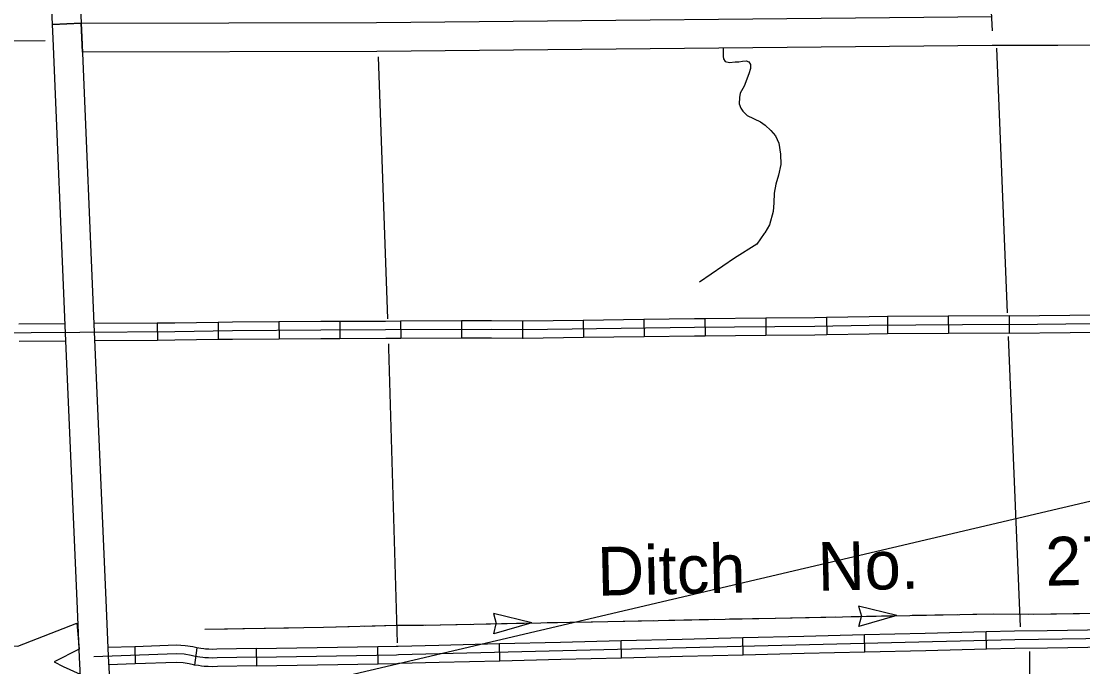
# Model space of a CAD drawing. Extents: x -5566 to 1759129, y -3726 to 731467.
# Drawn here: x -4997.6 to -4927.6, y 268.1 to 310.6 of the extents above; entities that cross this region are included whole.
import ezdxf

# ---------------------------------------------------------------- set-up
doc = ezdxf.new("R2010")
doc.units = 0
doc.layers.add('Default', color=7, linetype='Continuous')

msp = doc.modelspace()

# ---------------------------------------------------------------- linework, layer by layer
at = {"layer": 'Default'}
for p, q in [((-5037.982, 253.015), (-4814.177, 305.513)), ((-4952.518, 291.013), (-4952.507, 289.874)), ((-4948.508, 291.051), (-4948.498, 289.911)), ((-4944.505, 291.095), (-4944.483, 289.956)), ((-4940.489, 291.158), (-4940.48, 290.019)), ((-4936.479, 291.189), (-4936.47, 290.05)), ((-4932.469, 291.219), (-4932.461, 290.08)), ((-4988.603, 290.73), (-4988.594, 289.591)), ((-4984.598, 290.783), (-4984.58, 289.644)), ((-4980.583, 290.815), (-4980.577, 289.675)), ((-4976.573, 290.836), (-4976.567, 289.696)), ((-4972.563, 290.855), (-4972.558, 289.716)), ((-4968.553, 290.874), (-4968.548, 289.735)), ((-4964.536, 290.868), (-4964.545, 289.729)), ((-4960.539, 290.916), (-4960.524, 289.777)), ((-4956.529, 290.966), (-4956.515, 289.827)), ((-4963.921, 270.989), (-4966.452, 271.613)), ((-4966.452, 271.613), (-4966.259, 270.947)), ((-4939.868, 271.47), (-4942.398, 272.094)), ((-4942.398, 272.094), (-4942.205, 271.428)), ((-4939.868, 271.47), (-4942.371, 270.745)), ((-4942.371, 270.745), (-4942.205, 271.419)), ((-4963.921, 270.989), (-4966.425, 270.264)), ((-4966.425, 270.264), (-4966.259, 270.938)), ((-4949.987, 268.888), (-4950.015, 270.027)), ((-4941.97, 269.086), (-4941.998, 270.224)), ((-4933.953, 269.283), (-4933.981, 270.422)), ((-4990.087, 269.423), (-4990.047, 268.285)), ((-4985.993, 269.343), (-4986.155, 268.215)), ((-4974.042, 268.304), (-4974.063, 269.443)), ((-4966.021, 268.494), (-4966.049, 269.633)), ((-4958.004, 268.691), (-4958.032, 269.83)), ((-4982.079, 269.298), (-4982.063, 268.159))]:
    msp.add_line(p, q, dxfattribs=at)
for points in [[(-4993.615, 310.476), (-4995.511, 310.392), (-4996.003, 321.585), (-4997.259, 349.695), (-4998.481, 377.677), (-4998.548, 379.506), (-4998.756, 386.137), (-4999.305, 409.605), (-4999.405, 414.253)], [(-4997.507, 414.294), (-4997.407, 409.647), (-4996.858, 386.189), (-4996.65, 379.571), (-4996.584, 377.753), (-4995.362, 349.779), (-4994.106, 321.669), (-4993.615, 310.476)], [(-4935.136, 340.268), (-4934.932, 340.239), (-4934.712, 340.118), (-4934.597, 339.963), (-4934.55, 339.818), (-4934.52, 339.683), (-4934.512, 339.514), (-4934.542, 339.298), (-4934.537, 339.124), (-4934.44, 333.834), (-4934.306, 328.927), (-4934.137, 324.131), (-4933.786, 313.783), (-4933.595, 309.971)], [(-4894.213, 311.471), (-4894.177, 309.573), (-4894.454, 309.568), (-4900.14, 309.548), (-4902.933, 309.43), (-4913.232, 309.209), (-4915.299, 309.191), (-4922.772, 309.057), (-4929.257, 309.022), (-4933.595, 309.022)], [(-4993.533, 308.577), (-4993.615, 310.476), (-4974.148, 310.525), (-4933.595, 310.92)], [(-4995.511, 310.392), (-4993.615, 310.476), (-4993.575, 309.565), (-4992.757, 290.162), (-4991.964, 271.99), (-4991.839, 268.804), (-4991.604, 264.558), (-4990.974, 248.26), (-4990.443, 236.483), (-4990.139, 228.112)], [(-4992.036, 228.043), (-4992.34, 236.405), (-4992.871, 248.181), (-4993.501, 264.469), (-4993.735, 268.714), (-4993.861, 271.911), (-4994.654, 290.081), (-4995.471, 309.483), (-4995.511, 310.392)], [(-4932.093, 269.898), (-4922.733, 270.032), (-4914.418, 270.04), (-4914.277, 270.034), (-4914.082, 270.022), (-4913.941, 269.997), (-4913.709, 269.942), (-4913.495, 269.906), (-4913.311, 269.869), (-4913.036, 269.851), (-4912.639, 269.9), (-4912.388, 269.942), (-4912.125, 270.004), (-4912.015, 270.052), (-4911.918, 270.138), (-4911.881, 270.23), (-4911.887, 270.371), (-4911.905, 270.731), (-4911.991, 272.12), (-4912.699, 290.852), (-4913.247, 310.158)], [(-5014.656, 309.149), (-5005.512, 309.311), (-4995.997, 309.342)], [(-4933.595, 309.022), (-4974.136, 308.626), (-4993.533, 308.577)], [(-4951.316, 308.849), (-4951.322, 308.301), (-4951.286, 308.134), (-4951.184, 307.963), (-4950.898, 307.895), (-4950.522, 307.944), (-4950.274, 307.939), (-4950.041, 307.983), (-4949.796, 308.012), (-4949.626, 307.943), (-4949.507, 307.756), (-4949.504, 307.504), (-4949.626, 307.14), (-4949.935, 306.33)], [(-4933.309, 308.843), (-4932.596, 291.415)], [(-4974.038, 308.258), (-4973.428, 291.024)], [(-4949.935, 306.33), (-4950.186, 305.877), (-4950.242, 305.585), (-4950.248, 305.18), (-4950.153, 304.893), (-4950.007, 304.686), (-4949.722, 304.408), (-4948.852, 303.986), (-4948.547, 303.777), (-4948.166, 303.411), (-4947.87, 303.057), (-4947.637, 302.578), (-4947.524, 301.85), (-4947.519, 301.17), (-4947.672, 300.469), (-4947.846, 299.874), (-4947.959, 299.297), (-4947.97, 298.655), (-4948.023, 298.08), (-4948.268, 297.207), (-4948.558, 296.676), (-4948.611, 296.624), (-4949.084, 295.925), (-4950.568, 295.016), (-4952.874, 293.439)], [(-4952.518, 291.013), (-4953.202, 291.007), (-4956.529, 290.966)], [(-4948.508, 291.051), (-4952.518, 291.013)], [(-4944.505, 291.095), (-4945.278, 291.081), (-4948.508, 291.051)], [(-4940.489, 291.158), (-4941.696, 291.149), (-4944.505, 291.095)], [(-4936.479, 291.189), (-4940.489, 291.158)], [(-4932.469, 291.219), (-4936.479, 291.189)], [(-4932.469, 291.219), (-4928.462, 291.262)], [(-4928.462, 291.262), (-4924.452, 291.306)], [(-4994.679, 290.684), (-4997.719, 290.661)], [(-4932.465, 290.65), (-4941.688, 290.58), (-4945.27, 290.511), (-4953.196, 290.437), (-4964.484, 290.298), (-4966.576, 290.314), (-4973.552, 290.281), (-4977.83, 290.26), (-4983.643, 290.228), (-4987.447, 290.169), (-4993.705, 290.121)], [(-4988.603, 290.73), (-4992.779, 290.698)], [(-4984.598, 290.783), (-4987.454, 290.738), (-4988.603, 290.73)], [(-4980.583, 290.815), (-4983.649, 290.798), (-4984.598, 290.783)], [(-4976.573, 290.836), (-4977.833, 290.829), (-4980.583, 290.815)], [(-4972.563, 290.855), (-4973.554, 290.85), (-4976.573, 290.836)], [(-4968.553, 290.874), (-4972.563, 290.855)], [(-4964.536, 290.868), (-4966.575, 290.884), (-4968.553, 290.874)], [(-4960.539, 290.916), (-4964.485, 290.868), (-4964.536, 290.868)], [(-4956.529, 290.966), (-4960.539, 290.916)], [(-4932.465, 290.65), (-4923.163, 290.75), (-4912.699, 290.852)], [(-4993.705, 290.121), (-5009.708, 290), (-5010.205, 289.956), (-5010.678, 289.894), (-5011.158, 289.828), (-5011.69, 289.749), (-5012.214, 289.661), (-5012.995, 289.454), (-5013.768, 289.196), (-5014.458, 288.94), (-5014.999, 288.722), (-5015.413, 288.535), (-5015.671, 288.419), (-5016.467, 287.979), (-5018.023, 286.931), (-5036.624, 273.349), (-5039.143, 271.485), (-5040.285, 270.723), (-5040.649, 270.529), (-5041.1, 270.226), (-5041.309, 270.024), (-5041.41, 269.807), (-5041.457, 269.628)], [(-4988.594, 289.591), (-4992.73, 289.559)], [(-4984.58, 289.644), (-4987.44, 289.599), (-4988.594, 289.591)], [(-4980.577, 289.675), (-4983.637, 289.659), (-4984.58, 289.644)], [(-4976.567, 289.696), (-4977.827, 289.69), (-4980.577, 289.675)], [(-4972.558, 289.716), (-4973.549, 289.711), (-4976.567, 289.696)], [(-4968.548, 289.735), (-4972.558, 289.716)], [(-4964.545, 289.729), (-4966.577, 289.745), (-4968.548, 289.735)], [(-4960.524, 289.777), (-4964.483, 289.728), (-4964.545, 289.729)], [(-4956.515, 289.827), (-4960.524, 289.777)], [(-4952.507, 289.874), (-4953.19, 289.868), (-4956.515, 289.827)], [(-4948.498, 289.911), (-4952.507, 289.874)], [(-4944.483, 289.956), (-4945.262, 289.941), (-4948.498, 289.911)], [(-4940.48, 290.019), (-4941.68, 290.01), (-4944.483, 289.956)], [(-4936.47, 290.05), (-4940.48, 290.019)], [(-4932.461, 290.08), (-4936.47, 290.05)], [(-4932.531, 289.842), (-4931.749, 270.735)], [(-4932.459, 290.08), (-4928.449, 290.123)], [(-4928.449, 290.123), (-4924.44, 290.167)], [(-4994.63, 289.545), (-4997.71, 289.521)], [(-4973.369, 289.366), (-4973.359, 289.08), (-4972.803, 269.681)], [(-4985.469, 270.571), (-4977.649, 270.703), (-4972.841, 270.847), (-4971.058, 270.847), (-4933.509, 271.597), (-4931.175, 271.558)], [(-4942.874, 271.41), (-4939.868, 271.47)], [(-4938.866, 271.49), (-4937.362, 271.52)], [(-4937.362, 271.52), (-4935.859, 271.55)], [(-4934.857, 271.57), (-4933.509, 271.597), (-4931.85, 271.57)], [(-4931.175, 271.558), (-4916.597, 271.788), (-4912.586, 271.557), (-4911.247, 270.793)], [(-4930.848, 271.564), (-4927.841, 271.611)], [(-5019.032, 269.984), (-5016.718, 269.908), (-4997.779, 269.465), (-4993.903, 270.979), (-4993.756, 269.252)], [(-4978.954, 270.681), (-4977.649, 270.703), (-4975.948, 270.754)], [(-4974.946, 270.784), (-4972.841, 270.847), (-4971.939, 270.847)], [(-4970.937, 270.849), (-4967.93, 270.909)], [(-4966.928, 270.929), (-4963.921, 270.989)], [(-4962.919, 271.009), (-4961.416, 271.039)], [(-4961.416, 271.039), (-4959.912, 271.069)], [(-4958.91, 271.089), (-4955.904, 271.149)], [(-4954.901, 271.169), (-4951.895, 271.229)], [(-4950.892, 271.249), (-4947.886, 271.309)], [(-4946.883, 271.33), (-4943.877, 271.39)], [(-4985.469, 270.571), (-4983.966, 270.597)], [(-4982.963, 270.614), (-4979.956, 270.664)], [(-4954.024, 269.929), (-4950.015, 270.027)], [(-4950.015, 270.027), (-4946.007, 270.126)], [(-4946.007, 270.126), (-4941.998, 270.224)], [(-4941.998, 270.224), (-4937.99, 270.323)], [(-4937.99, 270.323), (-4933.981, 270.422)], [(-4933.981, 270.422), (-4932.104, 270.468), (-4929.966, 270.498)], [(-4929.966, 270.498), (-4925.957, 270.555)], [(-4990.087, 269.423), (-4991.861, 269.361)], [(-4985.993, 269.343), (-4985.995, 269.343), (-4986.263, 269.409), (-4986.771, 269.491), (-4987.342, 269.519), (-4990.087, 269.423)], [(-4982.079, 269.298), (-4984.669, 269.26), (-4984.947, 269.247), (-4985.196, 269.26), (-4985.419, 269.266), (-4985.532, 269.281), (-4985.728, 269.305), (-4985.993, 269.343)], [(-4982.079, 269.298), (-4978.072, 269.37)], [(-4982.071, 268.728), (-4972.838, 268.896), (-4972.709, 268.899), (-4932.093, 269.898)], [(-4978.072, 269.37), (-4974.063, 269.443)], [(-4974.063, 269.443), (-4972.851, 269.465), (-4972.724, 269.469), (-4970.058, 269.534)], [(-4970.058, 269.534), (-4966.049, 269.633)], [(-4966.049, 269.633), (-4962.041, 269.731)], [(-4962.041, 269.731), (-4958.032, 269.83)], [(-4958.032, 269.83), (-4954.024, 269.929)], [(-4933.953, 269.283), (-4932.082, 269.329), (-4929.95, 269.359)], [(-4929.95, 269.359), (-4925.941, 269.416)], [(-4993.756, 269.252), (-4995.394, 268.433)], [(-4982.071, 268.728), (-4984.651, 268.691), (-4984.948, 268.676), (-4985.219, 268.691), (-4985.464, 268.697), (-4985.604, 268.716), (-4985.804, 268.74), (-4986.104, 268.783), (-4986.377, 268.85), (-4986.831, 268.924), (-4987.346, 268.949), (-4992.787, 268.759)], [(-4962.013, 268.593), (-4958.004, 268.691)], [(-4958.004, 268.691), (-4953.996, 268.79)], [(-4953.996, 268.79), (-4949.987, 268.888)], [(-4949.987, 268.888), (-4945.979, 268.987)], [(-4945.979, 268.987), (-4941.97, 269.086)], [(-4941.97, 269.086), (-4937.962, 269.184)], [(-4937.962, 269.184), (-4933.953, 269.283)], [(-4930.948, 228.974), (-4930.972, 249.586), (-4931.103, 269.1)], [(-4995.394, 268.433), (-4994.798, 268.126), (-4993.675, 267.615), (-4993.548, 265.483)], [(-4990.047, 268.285), (-4991.807, 268.223)], [(-4986.155, 268.215), (-4986.213, 268.223), (-4986.491, 268.292), (-4986.89, 268.357), (-4987.349, 268.379), (-4990.047, 268.285)], [(-4982.063, 268.159), (-4984.633, 268.122), (-4984.949, 268.106), (-4985.241, 268.121), (-4985.508, 268.129), (-4985.676, 268.151), (-4985.879, 268.175), (-4986.155, 268.215)], [(-4982.063, 268.159), (-4978.051, 268.232)], [(-4978.051, 268.232), (-4974.042, 268.304)], [(-4974.042, 268.304), (-4972.825, 268.326), (-4972.695, 268.33), (-4970.03, 268.395)], [(-4970.03, 268.395), (-4966.021, 268.494)], [(-4966.021, 268.494), (-4962.013, 268.593)]]:
    msp.add_lwpolyline(points, dxfattribs=at)

# ---------------------------------------------------------------- texts
msp.add_text('Ditch    No.       27', height=3.20475, rotation=1.26819, dxfattribs=at).set_placement((-4959.574, 272.779))

doc.saveas('drawing.dxf')
